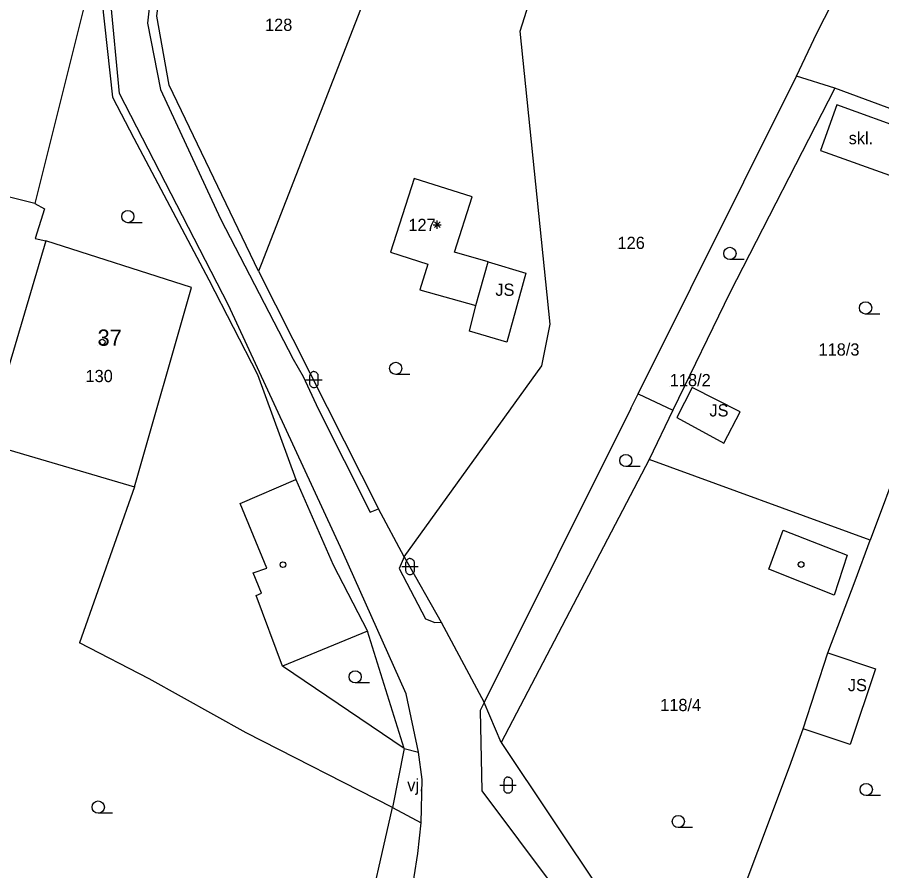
# Model space of a CAD drawing. Extents: x -836739 to -835945, y -1070775 to -1070126.
# Drawn here: x -836548.7 to -836495.7, y -1070449 to -1070396.6 of the extents above; entities that cross this region are included whole.
import ezdxf

# ---------------------------------------------------------------- set-up
doc = ezdxf.new("R2010")
doc.units = 0
for name, color, linetype in [('BodPole_mer', 7, 'Continuous'), ('Budovy_hranice', 7, 'Continuous'), ('Budovy_kody', 7, 'Continuous'), ('Doprava_hranice', 7, 'Continuous'), ('Doprava_kody', 7, 'Continuous'), ('OstPloch_hranice', 7, 'Continuous'), ('OstPloch_kody', 7, 'Continuous'), ('RuianAdr_popis', 7, 'Continuous'), ('RuianPar_popis', 7, 'Continuous'), ('Stavby_hr_stav', 7, 'Continuous'), ('Stavby_kody', 7, 'Continuous'), ('Stavby_linie', 7, 'Continuous')]:
    doc.layers.add(name, color=color, linetype=linetype)

msp = doc.modelspace()

# ---------------------------------------------------------------- linework, layer by layer
at = {"layer": 'BodPole_mer'}
for p, q in [((-836540.74, -1070396.93), (-836540.74, -1070396.93)), ((-836517.87, -1070397.43), (-836517.87, -1070397.43)), ((-836499.66, -1070397.56), (-836499.66, -1070397.56)), ((-836500.91, -1070400.2), (-836500.91, -1070400.2)), ((-836539.94, -1070401), (-836539.94, -1070401)), ((-836539.42, -1070400.74), (-836539.42, -1070400.74)), ((-836498.55, -1070400.92), (-836498.55, -1070400.92)), ((-836542.9, -1070401.49), (-836542.9, -1070401.49)), ((-836542.47, -1070401.26), (-836542.47, -1070401.26)), ((-836498.42, -1070401.95), (-836498.42, -1070401.95)), ((-836541.59, -1070404), (-836541.59, -1070404)), ((-836499.43, -1070404.75), (-836499.43, -1070404.75)), ((-836524.38, -1070406.47), (-836524.38, -1070406.47)), ((-836547.67, -1070408.02), (-836547.67, -1070408.02)), ((-836520.81, -1070407.61), (-836520.81, -1070407.61)), ((-836547.06, -1070408.33), (-836547.06, -1070408.33)), ((-836536.26, -1070408.95), (-836536.26, -1070408.95)), ((-836547.65, -1070410.15), (-836547.65, -1070410.15)), ((-836546.99, -1070410.3), (-836546.99, -1070410.3)), ((-836525.83, -1070410.99), (-836525.83, -1070410.99)), ((-836521.9, -1070410.99), (-836521.9, -1070410.99)), ((-836533.76, -1070411.76), (-836533.76, -1070411.76)), ((-836523.53, -1070411.73), (-836523.53, -1070411.73)), ((-836519.83, -1070411.6), (-836519.83, -1070411.6)), ((-836533.93, -1070412.16), (-836533.93, -1070412.16)), ((-836517.51, -1070412.29), (-836517.51, -1070412.29)), ((-836536.99, -1070412.69), (-836536.99, -1070412.69)), ((-836538.04, -1070413.16), (-836538.04, -1070413.16)), ((-836524.03, -1070413.31), (-836524.03, -1070413.31)), ((-836505, -1070413.5), (-836505, -1070413.5)), ((-836535.78, -1070414.25), (-836535.78, -1070414.25)), ((-836520.58, -1070414.27), (-836520.58, -1070414.27)), ((-836516.02, -1070415.43), (-836516.02, -1070415.43)), ((-836520.98, -1070415.85), (-836520.98, -1070415.85)), ((-836518.69, -1070416.52), (-836518.69, -1070416.52)), ((-836531.81, -1070417.56), (-836531.81, -1070417.56)), ((-836516.53, -1070417.97), (-836516.53, -1070417.97)), ((-836533.99, -1070418.52), (-836533.99, -1070418.52)), ((-836531.19, -1070418.64), (-836531.19, -1070418.64)), ((-836510.63, -1070419.69), (-836510.63, -1070419.69)), ((-836507.3, -1070419.3), (-836507.3, -1070419.3)), ((-836530.26, -1070420.61), (-836530.26, -1070420.61)), ((-836511.08, -1070420.6), (-836511.08, -1070420.6)), ((-836508.49, -1070420.71), (-836508.49, -1070420.71)), ((-836504.37, -1070420.8), (-836504.37, -1070420.8)), ((-836508.26, -1070421.15), (-836508.26, -1070421.15)), ((-836505.36, -1070422.73), (-836505.36, -1070422.73)), ((-836509.95, -1070423.73), (-836509.95, -1070423.73)), ((-836531.63, -1070424.96), (-836531.63, -1070424.96)), ((-836541.54, -1070425.41), (-836541.54, -1070425.41)), ((-836535.06, -1070426.43), (-836535.06, -1070426.43)), ((-836527.07, -1070426.97), (-836527.07, -1070426.97)), ((-836526.57, -1070426.77), (-836526.57, -1070426.77)), ((-836501.73, -1070428.08), (-836501.73, -1070428.08)), ((-836496.39, -1070428.69), (-836496.39, -1070428.69)), ((-836528.78, -1070429.39), (-836528.78, -1070429.39)), ((-836524.99, -1070429.71), (-836524.99, -1070429.71)), ((-836497.79, -1070429.61), (-836497.79, -1070429.61)), ((-836529.35, -1070430.2), (-836529.35, -1070430.2)), ((-836534.26, -1070430.69), (-836534.26, -1070430.69)), ((-836533.41, -1070430.41), (-836533.41, -1070430.41)), ((-836525.29, -1070430.43), (-836525.29, -1070430.43)), ((-836502.61, -1070430.46), (-836502.61, -1070430.46)), ((-836497.3, -1070431.18), (-836497.3, -1070431.18)), ((-836533.75, -1070431.95), (-836533.75, -1070431.95)), ((-836534.07, -1070432.08), (-836534.07, -1070432.08)), ((-836498.6, -1070432.07), (-836498.6, -1070432.07)), ((-836523.67, -1070433.51), (-836523.67, -1070433.51)), ((-836523.11, -1070433.75), (-836523.11, -1070433.75)), ((-836522.71, -1070433.72), (-836522.71, -1070433.72)), ((-836527.24, -1070434.28), (-836527.24, -1070434.28)), ((-836544.92, -1070434.98), (-836544.92, -1070434.98)), ((-836498.99, -1070435.6), (-836498.99, -1070435.6)), ((-836532.46, -1070436.42), (-836532.46, -1070436.42)), ((-836496.06, -1070436.58), (-836496.06, -1070436.58)), ((-836540.65, -1070437.21), (-836540.65, -1070437.21)), ((-836524.87, -1070438.13), (-836524.87, -1070438.13)), ((-836520.08, -1070438.65), (-836520.08, -1070438.65)), ((-836520.32, -1070439.15), (-836520.32, -1070439.15)), ((-836500.5, -1070440.27), (-836500.5, -1070440.27)), ((-836534.69, -1070440.52), (-836534.69, -1070440.52)), ((-836524.98, -1070441.47), (-836524.98, -1070441.47)), ((-836519.03, -1070441.12), (-836519.03, -1070441.12)), ((-836497.61, -1070441.23), (-836497.61, -1070441.23)), ((-836524.1, -1070441.71), (-836524.1, -1070441.71)), ((-836501.33, -1070442.61), (-836501.33, -1070442.61)), ((-836523.89, -1070443.38), (-836523.89, -1070443.38)), ((-836520.23, -1070444.07), (-836520.23, -1070444.07)), ((-836525.7, -1070445.11), (-836525.7, -1070445.11)), ((-836523.94, -1070446.04), (-836523.94, -1070446.04)), ((-836524.15, -1070447.92), (-836524.15, -1070447.92))]:
    msp.add_line(p, q, dxfattribs=at)
at = {"layer": 'Budovy_hranice'}
for points in [[(-836547.67, -1070408.02), (-836561.18, -1070404.66), (-836558.85, -1070395.08), (-836554.33, -1070396.22), (-836554.25, -1070395.86), (-836553.6, -1070393.14), (-836553.41, -1070392.35), (-836544.32, -1070394.64), (-836547.67, -1070408.02)], [(-836524.03, -1070413.31), (-836520.58, -1070414.27), (-836519.83, -1070411.6), (-836521.9, -1070410.99), (-836520.81, -1070407.61), (-836524.38, -1070406.47), (-836525.83, -1070410.99), (-836523.53, -1070411.73), (-836524.03, -1070413.31)], [(-836546.99, -1070410.3), (-836550.67, -1070422.72), (-836541.54, -1070425.41), (-836538.04, -1070413.16), (-836546.99, -1070410.3)], [(-836527.24, -1070434.28), (-836532.46, -1070436.42), (-836534.07, -1070432.08), (-836533.75, -1070431.95), (-836534.26, -1070430.69), (-836533.41, -1070430.41), (-836535.06, -1070426.43), (-836531.63, -1070424.96)], [(-836531.63, -1070424.96), (-836529.35, -1070430.2), (-836527.24, -1070434.28)], [(-836497.79, -1070429.61), (-836498.6, -1070432.07), (-836502.61, -1070430.46), (-836501.73, -1070428.08), (-836497.79, -1070429.61)]]:
    msp.add_lwpolyline(points, dxfattribs=at)
at = {"layer": 'Budovy_kody'}
for p, q in [((-836522.783, -1070409.487), (-836523.137, -1070409.133)), ((-836522.783, -1070409.133), (-836523.137, -1070409.487)), ((-836522.96, -1070409.56), (-836522.96, -1070409.06)), ((-836523.21, -1070409.31), (-836522.71, -1070409.31))]:
    msp.add_line(p, q, dxfattribs=at)
for centre in [(-836543.53, -1070416.52), (-836532.43, -1070430.19), (-836500.62, -1070430.18)]:
    msp.add_circle(centre, 0.175, dxfattribs=at)
at = {"layer": 'Doprava_hranice'}
for p, q in [((-836524.98, -1070441.47), (-836524.1, -1070441.71)), ((-836525.7, -1070445.11), (-836523.94, -1070446.04))]:
    msp.add_line(p, q, dxfattribs=at)
for points in [[(-836536.74, -1070383), (-836537.35, -1070383.22), (-836539.98, -1070391.55), (-836540.43, -1070394.17), (-836540.74, -1070396.93), (-836539.94, -1070401), (-836536.26, -1070408.95), (-836531.81, -1070417.56), (-836531.19, -1070418.64), (-836530.26, -1070420.61), (-836527.07, -1070426.97), (-836526.57, -1070426.77)], [(-836531.1, -1070469.82), (-836529.4, -1070467.3), (-836528.17, -1070465.13), (-836524.83, -1070452.23), (-836524.15, -1070447.92), (-836523.94, -1070446.04), (-836523.89, -1070443.38), (-836524.1, -1070441.71), (-836524.87, -1070438.13), (-836528.78, -1070429.39), (-836535.78, -1070414.25), (-836542.47, -1070401.26), (-836543.02, -1070395.42), (-836542.75, -1070393.88), (-836540.03, -1070384.3)], [(-836524.99, -1070429.71), (-836525.29, -1070430.43), (-836523.67, -1070433.51), (-836523.11, -1070433.75), (-836522.71, -1070433.72)], [(-836520.08, -1070438.65), (-836520.32, -1070439.15), (-836520.23, -1070444.07), (-836509.08, -1070458.97)]]:
    msp.add_lwpolyline(points, dxfattribs=at)
at = {"layer": 'OstPloch_hranice'}
msp.add_line((-836519.03, -1070441.12), (-836520.08, -1070438.65), dxfattribs=at)
at = {"layer": 'OstPloch_kody'}
for p, q in [((-836541.075, -1070409.19), (-836541.95, -1070409.19)), ((-836504.115, -1070411.45), (-836504.99, -1070411.45)), ((-836495.785, -1070414.8), (-836496.66, -1070414.8)), ((-836530.78, -1070419.08), (-836530.78, -1070418.58)), ((-836530.28, -1070418.58), (-836530.28, -1070419.08)), ((-836524.635, -1070418.51), (-836525.51, -1070418.51)), ((-836531.03, -1070418.83), (-836530.03, -1070418.83)), ((-836510.505, -1070424.17), (-836511.38, -1070424.17)), ((-836525.13, -1070430.31), (-836524.13, -1070430.31)), ((-836524.88, -1070430.56), (-836524.88, -1070430.06)), ((-836524.38, -1070430.06), (-836524.38, -1070430.56)), ((-836527.125, -1070437.45), (-836528, -1070437.45)), ((-836518.86, -1070443.98), (-836518.86, -1070443.48)), ((-836518.36, -1070443.48), (-836518.36, -1070443.98)), ((-836519.11, -1070443.73), (-836518.11, -1070443.73)), ((-836495.745, -1070444.37), (-836496.62, -1070444.37)), ((-836542.895, -1070445.45), (-836543.77, -1070445.45)), ((-836507.285, -1070446.34), (-836508.16, -1070446.34))]:
    msp.add_line(p, q, dxfattribs=at)
for points in [[(-836530.53, -1070418.33), (-836530.575, -1070418.334), (-836530.622, -1070418.348), (-836530.667, -1070418.371), (-836530.707, -1070418.403), (-836530.739, -1070418.443), (-836530.762, -1070418.488), (-836530.776, -1070418.535), (-836530.78, -1070418.58)], [(-836530.53, -1070418.33), (-836530.485, -1070418.334), (-836530.438, -1070418.348), (-836530.393, -1070418.371), (-836530.353, -1070418.403), (-836530.321, -1070418.443), (-836530.298, -1070418.488), (-836530.284, -1070418.535), (-836530.28, -1070418.58)], [(-836530.53, -1070419.33), (-836530.575, -1070419.326), (-836530.622, -1070419.312), (-836530.667, -1070419.289), (-836530.707, -1070419.257), (-836530.739, -1070419.217), (-836530.762, -1070419.172), (-836530.776, -1070419.125), (-836530.78, -1070419.08)], [(-836530.28, -1070419.08), (-836530.284, -1070419.125), (-836530.298, -1070419.172), (-836530.321, -1070419.217), (-836530.353, -1070419.257), (-836530.393, -1070419.289), (-836530.438, -1070419.312), (-836530.485, -1070419.326), (-836530.53, -1070419.33)], [(-836524.63, -1070429.81), (-836524.675, -1070429.814), (-836524.722, -1070429.828), (-836524.767, -1070429.851), (-836524.807, -1070429.883), (-836524.839, -1070429.923), (-836524.862, -1070429.968), (-836524.876, -1070430.015), (-836524.88, -1070430.06)], [(-836524.63, -1070429.81), (-836524.585, -1070429.814), (-836524.538, -1070429.828), (-836524.493, -1070429.851), (-836524.453, -1070429.883), (-836524.421, -1070429.923), (-836524.398, -1070429.968), (-836524.384, -1070430.015), (-836524.38, -1070430.06)], [(-836524.63, -1070430.81), (-836524.675, -1070430.806), (-836524.722, -1070430.792), (-836524.767, -1070430.769), (-836524.807, -1070430.737), (-836524.839, -1070430.697), (-836524.862, -1070430.652), (-836524.876, -1070430.605), (-836524.88, -1070430.56)], [(-836524.38, -1070430.56), (-836524.384, -1070430.605), (-836524.398, -1070430.652), (-836524.421, -1070430.697), (-836524.453, -1070430.737), (-836524.493, -1070430.769), (-836524.538, -1070430.792), (-836524.585, -1070430.806), (-836524.63, -1070430.81)], [(-836518.61, -1070443.23), (-836518.655, -1070443.234), (-836518.702, -1070443.248), (-836518.747, -1070443.271), (-836518.787, -1070443.303), (-836518.819, -1070443.343), (-836518.842, -1070443.388), (-836518.856, -1070443.435), (-836518.86, -1070443.48)], [(-836518.61, -1070443.23), (-836518.565, -1070443.234), (-836518.518, -1070443.248), (-836518.473, -1070443.271), (-836518.433, -1070443.303), (-836518.401, -1070443.343), (-836518.378, -1070443.388), (-836518.364, -1070443.435), (-836518.36, -1070443.48)], [(-836518.61, -1070444.23), (-836518.655, -1070444.226), (-836518.702, -1070444.212), (-836518.747, -1070444.189), (-836518.787, -1070444.157), (-836518.819, -1070444.117), (-836518.842, -1070444.072), (-836518.856, -1070444.025), (-836518.86, -1070443.98)], [(-836518.36, -1070443.98), (-836518.364, -1070444.025), (-836518.378, -1070444.072), (-836518.401, -1070444.117), (-836518.433, -1070444.157), (-836518.473, -1070444.189), (-836518.518, -1070444.212), (-836518.565, -1070444.226), (-836518.61, -1070444.23)]]:
    msp.add_lwpolyline(points, dxfattribs=at)
for centre in [(-836541.95, -1070408.815), (-836504.99, -1070411.075), (-836496.66, -1070414.425), (-836525.51, -1070418.135), (-836511.38, -1070423.795), (-836528, -1070437.075), (-836496.62, -1070443.995), (-836543.77, -1070445.075), (-836508.16, -1070445.965)]:
    msp.add_ellipse(centre, major_axis=(0.375, 0), ratio=0.999999, dxfattribs=at)
at = {"layer": 'RuianAdr_popis'}
msp.add_line((-836543.81, -1070416.75), (-836543.81, -1070416.75), dxfattribs=at)
at = {"layer": 'RuianPar_popis'}
for p, q in [((-836533.53, -1070397.41), (-836533.53, -1070397.41)), ((-836524.73, -1070409.7), (-836524.73, -1070409.7)), ((-836511.89, -1070410.8), (-836511.89, -1070410.8)), ((-836499.55, -1070417.35), (-836499.55, -1070417.35)), ((-836544.55, -1070418.98), (-836544.55, -1070418.98)), ((-836508.68, -1070419.23), (-836508.68, -1070419.23)), ((-836509.27, -1070439.18), (-836509.27, -1070439.18))]:
    msp.add_line(p, q, dxfattribs=at)
at = {"layer": 'Stavby_hr_stav'}
for points in [[(-836498.42, -1070401.95), (-836499.43, -1070404.75), (-836494.91, -1070406.38), (-836493.9, -1070403.58), (-836498.42, -1070401.95)], [(-836519.83, -1070411.6), (-836517.51, -1070412.29), (-836518.69, -1070416.52), (-836520.98, -1070415.85), (-836520.58, -1070414.27)], [(-836505.36, -1070422.73), (-836504.37, -1070420.8), (-836507.3, -1070419.3), (-836508.26, -1070421.15), (-836505.36, -1070422.73)], [(-836498.99, -1070435.6), (-836496.06, -1070436.58), (-836497.61, -1070441.23), (-836500.5, -1070440.27), (-836498.99, -1070435.6)]]:
    msp.add_lwpolyline(points, dxfattribs=at)
at = {"layer": 'Stavby_linie'}
for p, q in [((-836517.87, -1070397.43), (-836514.6, -1070387.21)), ((-836516.02, -1070415.43), (-836517.87, -1070397.43)), ((-836498.55, -1070400.92), (-836500.91, -1070400.2)), ((-836533.93, -1070412.16), (-836526.57, -1070426.77)), ((-836516.53, -1070417.97), (-836516.02, -1070415.43)), ((-836524.99, -1070429.71), (-836516.53, -1070417.97)), ((-836510.63, -1070419.69), (-836508.49, -1070420.71)), ((-836492.95, -1070419.48), (-836496.39, -1070428.69)), ((-836511.08, -1070420.6), (-836520.08, -1070438.65)), ((-836541.54, -1070425.41), (-836544.92, -1070434.98)), ((-836524.99, -1070429.71), (-836526.57, -1070426.77)), ((-836524.99, -1070429.71), (-836522.71, -1070433.72)), ((-836522.71, -1070433.72), (-836520.08, -1070438.65)), ((-836524.98, -1070441.47), (-836527.24, -1070434.28)), ((-836524.98, -1070441.47), (-836532.46, -1070436.42)), ((-836524.98, -1070441.47), (-836525.7, -1070445.11))]:
    msp.add_line(p, q, dxfattribs=at)
for points in [[(-836500.91, -1070400.2), (-836499.66, -1070397.56), (-836496.79, -1070391.92), (-836494.43, -1070387.9), (-836493.04, -1070385.21)], [(-836533.93, -1070412.16), (-836539.42, -1070400.74), (-836540.18, -1070396.5), (-836539.69, -1070392.43)], [(-836544.32, -1070394.64), (-836543.66, -1070394.81), (-836543.54, -1070395.48), (-836542.9, -1070401.49), (-836541.59, -1070404), (-836536.99, -1070412.69)], [(-836527.25, -1070394.97), (-836533.76, -1070411.76), (-836533.93, -1070412.16)], [(-836470.4, -1070403.24), (-836483.68, -1070397.24), (-836487.03, -1070405.19), (-836498.55, -1070400.92)], [(-836511.08, -1070420.6), (-836510.63, -1070419.69), (-836500.91, -1070400.2)], [(-836498.55, -1070400.92), (-836505, -1070413.5), (-836508.49, -1070420.71), (-836509.95, -1070423.73)], [(-836547.67, -1070408.02), (-836547.06, -1070408.33), (-836547.65, -1070410.15), (-836546.99, -1070410.3)], [(-836536.99, -1070412.69), (-836533.99, -1070418.52), (-836531.63, -1070424.96)], [(-836496.39, -1070428.69), (-836509.95, -1070423.73), (-836519.03, -1070441.12)], [(-836498.99, -1070435.6), (-836497.3, -1070431.18), (-836496.39, -1070428.69)], [(-836525.7, -1070445.11), (-836534.69, -1070440.52), (-836540.65, -1070437.21), (-836544.92, -1070434.98)], [(-836507.11, -1070457.97), (-836501.33, -1070442.61), (-836500.5, -1070440.27)], [(-836519.03, -1070441.12), (-836512.81, -1070450.42), (-836507.11, -1070457.97)], [(-836535.29, -1070481.63), (-836535.24, -1070481.2), (-836534.16, -1070469.25), (-836530.49, -1070466.92), (-836529.34, -1070461.16), (-836525.7, -1070445.11)]]:
    msp.add_lwpolyline(points, dxfattribs=at)

# ---------------------------------------------------------------- texts
at = {"layer": 'Doprava_kody'}
msp.add_text('vj.', height=0.75, dxfattribs=at).set_placement((-836524.8, -1070444.1))
at = {"layer": 'RuianAdr_popis'}
msp.add_text('37', height=1, dxfattribs=at).set_placement((-836543.81, -1070416.75))
at = {"layer": 'RuianPar_popis'}
for s, p in [('128', (-836533.53, -1070397.41)), ('127', (-836524.73, -1070409.7)), ('126', (-836511.89, -1070410.8)), ('118/3', (-836499.55, -1070417.35)), ('130', (-836544.55, -1070418.98)), ('118/2', (-836508.68, -1070419.23)), ('118/4', (-836509.27, -1070439.18))]:
    msp.add_text(s, height=0.75, dxfattribs=at).set_placement(p)
at = {"layer": 'Stavby_kody'}
for s, p in [('skl.', (-836497.7, -1070404.37)), ('JS', (-836519.39, -1070413.68)), ('JS', (-836506.25, -1070421.09)), ('JS', (-836497.75, -1070437.96))]:
    msp.add_text(s, height=0.75, dxfattribs=at).set_placement(p)

doc.saveas('drawing.dxf')
